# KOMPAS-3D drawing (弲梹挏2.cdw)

Views: Вид 1, Вид 3, Вид 5, Вид 6
Referenced files in D:\Spawn\Учебные\Курсовики\Курсовик по ДМу\3 курс\Долудин\: Кран.cdw
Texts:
  Общий вид козлового крана
  Spawn
  Стандартные изделия
  Шайба 16Л ГОСТ 6402-70
  Гайка М22x1,5-6H ГОСТ 5915-70
  Шайба 22Л ГОСТ 6402-70
  Шайба 10Л ГОСТ 6402-70
  Шайба C 10.37 ГОСТ 10450-78
  Гайка М12x1,5-6H (S18) ГОСТ 5915-70
  Шайба 12Л ГОСТ 6402-70
  Гайка М16x1,5-6H ГОСТ 5915-70
  Болт М14x1,5-6gx16 (S21) ГОСТ 7798-70
  ACAD_ISO10W100_RGB_0_0_0_SC_1.000000.2
  ACAD_ISO10W100_RGB_0_0_0_SC_0.25_THICK_0.35
  POLYLINE_STYLE_0.18_RGB_0_0_0
  ACAD_ISO10W100_RGB_0_0_0_SC_1_THICK_0.35
  ACAD_ISO03W100_RGB_0_0_0_SC_0.5_THICK_0.35
  K5LT_BASIC_RGB_0_0_0_THICK_0.6
  K5LT_AXLED_RGB_0_0_0_SC_1_THICK_0.35
  Общий вид
  козлового крана
  Савченко В.В..
  Грачев А.А.
  СПбГПУ
  гр. 33221/2
Dimensions and other numbers on the sheet: 32000; 123; 12500; 4; 1:50; 2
